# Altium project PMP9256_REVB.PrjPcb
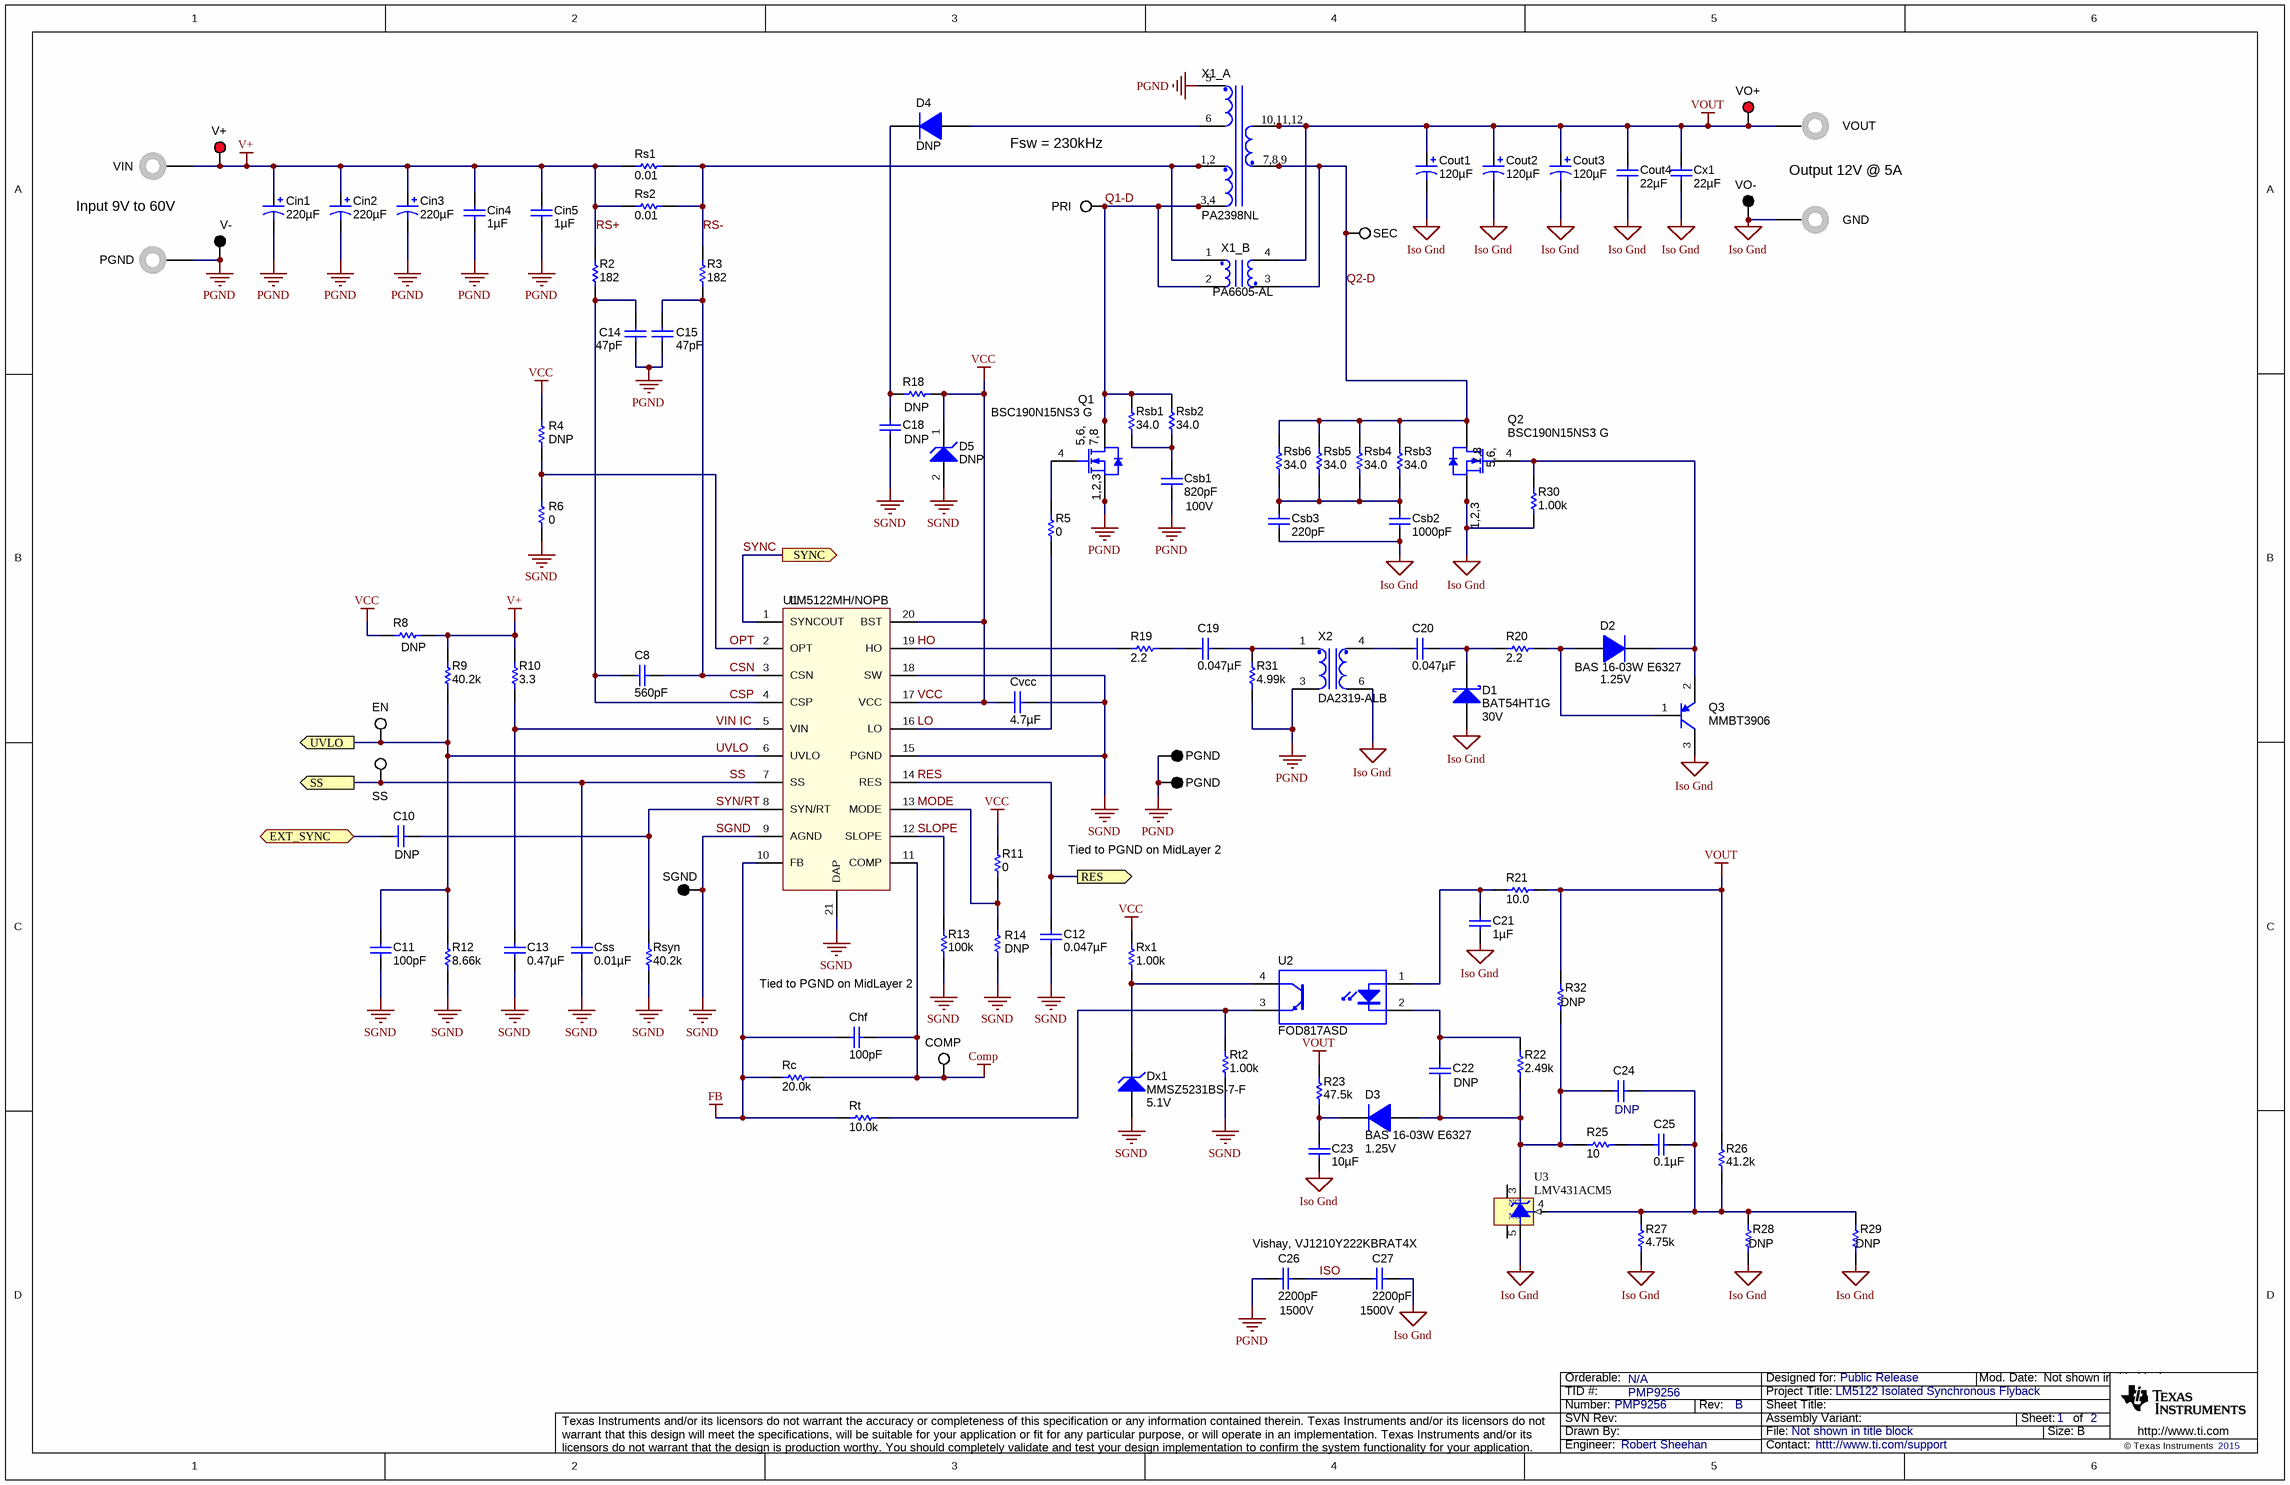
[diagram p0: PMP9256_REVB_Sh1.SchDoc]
CopyrightYear: 2015; EVM_Orderable: N/A; PCB_Layout: Robert Sheehan; PCB_Rev: B; PRJ_Customer: Public Release; PRJ_Engineer: Robert Sheehan; PRJ_Number: PMP9256; PRJ_Title: LM5122 Isolated Synchronous Flyback; SCH_Rev: B; TechSupport: httt://www.ti.com/support; TID: PMP9256
2 sheets, 119 parts. Net scope: flat (ports and power ports of the same name join across sheets).
Board file: PMP9256_REVB.PcbDoc
Sheets:
  PMP9256_REVB_Sh1.SchDoc
  PMP9256_REVB_Sh2.SchDoc

## Sheet PMP9256_REVB_Sh1.SchDoc
size 431 x 279 mm; Date: Not shown in title block; ApprovedBy: Not shown in title block; CheckedBy: Not shown in title block; Author: Not shown in title block; CompanyName: Not shown in title block; Engineer: Not shown in title block; Organization: Not shown in title block; Address1: Not shown in title block; Address2: Not shown in title block; Address3: Not shown in title block; Address4: Not shown in title block; DocumentNumber: 1; Revision: Use project parameter SCH_Rev; SheetNumber: 1; SheetTotal: 2; PageSetup: Record=PageOptions¦CenterHorizontal=True¦CenterVertical=True¦PrintScale=1.00¦XCorrection=1.00¦YCorrection=1.00¦PrintKind=0¦BorderSize=5000000¦LeftOffset=0¦BottomOffset=0¦Orientation=2¦PaperLength=1000¦PaperWidth=1000¦Scale=100¦PaperSource=15¦PrintQuality=600¦MediaType=1¦DitherType=10¦PaperKind=Letter¦PrintScaleMode=1

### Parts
C8  ValueDisplayed: 560pF  [0603L]  (hidden comment: GRM1885C1H561JA01D)
C10  DNP  [0603L]
C11  ValueDisplayed: 100pF  [0603L]  (hidden comment: GRM1885C1H101JA01D)
C12  ValueDisplayed: 0.047µF  [0603L]  (hidden comment: GRM188R71E473KA01D)
C13  ValueDisplayed: 0.47µF  [0603L]  (hidden comment: GRM188R71E474KA12D)
C14  ValueDisplayed: 47pF  [0603L]  (hidden comment: GRM1885C1H470JA01D)
C15  ValueDisplayed: 47pF  [0603L]  (hidden comment: GRM1885C1H470JA01D)
C18  DNP  [0805L]
C19  ValueDisplayed: 0.047µF  [0603L]  (hidden comment: GRM188R71E473KA01D)
C20  ValueDisplayed: 0.047µF  [0603L]  (hidden comment: GRM188R71E473KA01D)
C21  ValueDisplayed: 1µF  [0603L]  (hidden comment: C1608X7R1C105K)
C22  DNP  [0805L]
C23  ValueDisplayed: 10µF  [0805L]  (hidden comment: GRM21BR61C106KE15L)
C24  DNP  [0805L]
C25  ValueDisplayed: 0.1µF  [0603L]  (hidden comment: GRM188R71H104KA93D)
C26  Vishay, VJ1210Y222KBRAT4X  ValueDisplayed: 2200pF  Value2: 1500V  [1210L]
C27  ValueDisplayed: 2200pF  Value2: 1500V  [1210L]  (hidden comment: VJ1210Y222KXGAT5Z)
Chf  ValueDisplayed: 100pF  [0603L]  (hidden comment: GRM1885C1H101JA01D)
Cin1  ValueDisplayed: 220µF  [SM_RADIAL_H13]  (hidden comment: EEV-FK1J221Q)
Cin2  ValueDisplayed: 220µF  [SM_RADIAL_H13]  (hidden comment: EEV-FK1J221Q)
Cin3  ValueDisplayed: 220µF  [SM_RADIAL_H13]  (hidden comment: EEV-FK1J221Q)
Cin4  ValueDisplayed: 1µF  [1206L]  (hidden comment: C3216X7R2A105M)
Cin5  ValueDisplayed: 1µF  [1206L]  (hidden comment: C3216X7R2A105M)
COMP  5002  [Keystone5002]  (value not drawn)
Cout1  ValueDisplayed: 120µF  [CAPSMT_62_F61]  (hidden comment: 20SVPF120M)
Cout2  ValueDisplayed: 120µF  [CAPSMT_62_F61]  (hidden comment: 20SVPF120M)
Cout3  ValueDisplayed: 120µF  [CAPSMT_62_F61]  (hidden comment: 20SVPF120M)
Cout4  ValueDisplayed: 22µF  [1206L]  (hidden comment: GRM31CR61C226KE15L)
Csb1  ValueDisplayed: 820pF  Value2: 100V  [0603L]  (hidden comment: GRM188R72A821KA01D)
Csb2  value 1000pF  [0805]  (hidden comment: CGA4F3C0G2E102J085AA)
Csb3  value 220pF  [0603]  (hidden comment: CGA3E3C0G2E221J080AA)
Css  ValueDisplayed: 0.01µF  [0603L]  (hidden comment: GRM188R71H103KA01D)
Cvcc  ValueDisplayed: 4.7µF  [0603L]  (hidden comment: C0603C475K8PACTU)
Cx1  ValueDisplayed: 22µF  [1206L]  (hidden comment: GRM31CR61C226KE15L)
D1  BAT54HT1G  value 30V  [sod-323]
D2  BAS 16-03W E6327  value 1.25V  [sod-323]
D3  BAS 16-03W E6327  value 1.25V  [sod-323]
D4  DNP  [SOD-123]
D5  DNP  [SMA]
Dx1  MMSZ5231BS-7-F  value 5.1V  [sod-323]
EN  5002  [Keystone5002]  (value not drawn)
PGND  GND  [Keystone_575-4]
PGND2  PGND  [Keystone_575-4]
PGND3  PGND  [Keystone5011]
PGND4  PGND  [Keystone5011]
PRI  5002  [Keystone5002]  (value not drawn)
Q1  BSC190N15NS3 G  [PG-TDSON-8]
Q2  BSC190N15NS3 G  [PG-TDSON-8]
Q3  MMBT3906  [SOT-23]
R2  value 182  [0603L]  (hidden comment: CRCW0603182RFKEA)
R3  value 182  [0603L]  (hidden comment: CRCW0603182RFKEA)
R4  DNP  [0603L]
R5  value 0  [0603L]  (hidden comment: ERJ-3GEY0R00V)
R6  value 0  [0603L]  (hidden comment: ERJ-3GEY0R00V)
R8  DNP  [0603L]
R9  value 40.2k  [0603L]  (hidden comment: CRCW060340K2FKEA)
R10  value 3.3  [0603L]  (hidden comment: CRCW06033R30JNEA)
R11  value 0  [0603L]  (hidden comment: ERJ-3GEY0R00V)
R12  value 8.66k  [0603L]  (hidden comment: CRCW06038K66FKEA)
R13  value 100k  [0603L]  (hidden comment: CRCW0603100KFKEA)
R14  DNP  [0603L]
R18  DNP  [0603L]
R19  value 2.2  [0603L]  (hidden comment: CRCW06032R20JNEA)
R20  value 2.2  [0603L]  (hidden comment: CRCW06032R20JNEA)
R21  value 10.0  [0805L]  (hidden comment: CRCW080510R0FKEA)
R22  ValueDisplayed: 2.49k  [0603L]  (hidden comment: CRCW06032K49FKEA)
R23  value 47.5k  [0603L]  (hidden comment: CRCW060347K5FKEA)
R25  ValueDisplayed: 10  [0603L]  (hidden comment: CRCW060310R0JNEA)
R26  value 41.2k  [0603L]  (hidden comment: CRCW060341K2FKEA)
R27  ValueDisplayed: 4.75k  [0603L]  (hidden comment: CRCW06034K75FKEA)
R28  DNP  [0603L]
R29  DNP  [0603L]
R30  value 1.00k  [0603L]  (hidden comment: CRCW06031K00FKEA)
R31  value 4.99k  [0603L]  (hidden comment: CRCW06034K99FKEA)
R32  DNP  [0603L]
Rc  value 20.0k  [0603L]  (hidden comment: CRCW060320K0FKEA)
Rs1  value 0.01  [2010L]  (hidden comment: WSL2010R0100FEA18)
Rs2  value 0.01  [2010L]  (hidden comment: WSL2010R0100FEA18)
Rsb1  value 34.0  [1210L]  (hidden comment: ERJ-14NF34R0U)
Rsb2  value 34.0  [1210L]  (hidden comment: ERJ-14NF34R0U)
Rsb3  value 34.0  [1210L]  (hidden comment: ERJ-14NF34R0U)
Rsb4  value 34.0  [1210L]  (hidden comment: ERJ-14NF34R0U)
Rsb5  value 34.0  [1210L]  (hidden comment: ERJ-14NF34R0U)
Rsb6  value 34.0  [1210L]  (hidden comment: ERJ-14NF34R0U)
Rsyn  value 40.2k  [0603L]  (hidden comment: CRCW060340K2FKEA)
Rt  ValueDisplayed: 10.0k  [0603L]  (hidden comment: CRCW060310K0FKEA)
Rt2  ValueDisplayed: 1.00k  [0603L]  (hidden comment: CRCW06031K00FKEA)
Rx1  ValueDisplayed: 1.00k  [0603L]  (hidden comment: CRCW06031K00FKEA)
SEC  5002  [Keystone5002]  (value not drawn)
SGND  SGND  [Keystone5001]  (value not drawn)
SS  5002  [Keystone5002]  (value not drawn)
U1  LM5122MH/NOPB  [MXA20A_L]
U2  FOD817ASD  [N04C]
U3  LMV431ACM5  [MF05A_N]
V+  5010  [Keystone5010]  (value not drawn)
V-  5011  [Keystone5011]  (value not drawn)
VIN  575-4  [Keystone_575-4]  (value not drawn)
VO+  5010  [Keystone5010]  (value not drawn)
VO-  5011  [Keystone5011]  (value not drawn)
VOUT  Comment_1: Output 12V @ 5A  [Keystone_575-4]  (hidden comment: 575-4)
X1_A  PA2398NL
X1_B  PA6605-AL  [PA6605-AL]
X2  DA2319-ALB

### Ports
EXT_SYNC, RES, SS, SYNC (out), UVLO

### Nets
Comp: Chf.1 COMP.1 Rc.2 U1.11(COMP)
FB: Chf.2 Rc.1 Rt.2 U1.10(FB)
Iso Gnd: C21.2 C23.2 C27.1 Cout1.2(-) Cout2.2(-) Cout3.2(-) Cout4.2 Csb2.2 Csb3.2 Cx1.2 D1.2(A) PGND.1 Q2.1(S) Q2.2(S) Q2.3(S) Q3.3(C) R27.1 R28.1 R29.1 R30.1 U3.5(A) VO-.1 X2.6
PGND: C14.1 C15.2 C26.2 Cin1.2(-) Cin2.2(-) Cin3.2(-) Cin4.2 Cin5.2 Csb1.2 PGND2.1 PGND3.1 PGND4.1 Q1.1(S) Q1.2(S) Q1.3(S) R31.1 V-.1 X1_A.5 X2.3
SGND: C11.2 C12.2 C13.2 C18.2 Css.2 Cvcc.1 D5.2(A) Dx1.2(A) R6.1 R12.1 R13.1 R14.1 Rsyn.1 Rt2.1 SGND.1 U1.9(AGND) U1.15(PGND) U1.18(SW) U1.21(DAP)
V+: Cin1.1(+) Cin2.1(+) Cin3.1(+) Cin4.1 Cin5.1 R2.2 R8.1 R9.2 R10.2 Rs1.1 Rs2.1 V+.1 VIN.1
VCC: Cvcc.2 D5.1(K) R4.2 R8.2 R11.2 R18.1 Rx1.2 U1.17(VCC) U1.20(BST)
VOUT: Cout1.1(+) Cout2.1(+) Cout3.1(+) Cout4.1 Cx1.1 R21.2 R23.2 R26.2 R32.1 VO+.1 VOUT.1 X1_A.10 X1_A.11 X1_A.12 X1_B.4
CSN: C8.1 C15.1 R3.1 U1.3(CSN)
CSP: C8.2 C14.2 R2.1 U1.4(CSP)
EXT_SYNC: C10.2 ; port EXT_SYNC
HO: R19.1 U1.19(HO)
ISO: C26.1 C27.2
LO: R5.2 U1.16(LO)
MODE: R11.1 R14.2 U1.13(MODE)
OPT: R4.1 R6.2 U1.2(OPT)
Q1-D: PRI.1 Q1.5(D) Q1.6(D) Q1.7(D) Q1.8(D) Q1.9(D) Rsb1.2 Rsb2.2 X1_A.3 X1_A.4 X1_B.2
Q2-D: Q2.5(D) Q2.6(D) Q2.7(D) Q2.8(D) Q2.9(D) Rsb3.2 Rsb4.2 Rsb5.2 Rsb6.2 SEC.1 X1_A.7 X1_A.8 X1_A.9 X1_B.3
RES: C12.1 U1.14(RES) ; port RES
RS-: R3.2 Rs1.2 Rs2.2 X1_A.1 X1_A.2 X1_B.1
SLOPE: R13.2 U1.12(SLOPE)
SS: Css.1 SS.1 U1.7(SS) ; port SS
SYN/RT: C10.1 Rsyn.2 U1.8(SYN/RT)
SYNC: U1.1(SYNCOUT) ; port SYNC
UVLO: C11.1 EN.1 R9.1 R12.2 U1.6(UVLO) ; port UVLO
VIN IC: C13.1 R10.1 U1.5(VIN)
NetC18_1: C18.1 D4.1(K) R18.2
NetC19_1: C19.1 R31.2 X2.1
NetC19_2: C19.2 R19.2
NetC20_1: C20.1 D1.1(K) R20.1
NetC20_2: C20.2 X2.4
NetC21_1: C21.1 R21.1 U2.1(A)
NetC22_1: C22.1 C24.1 D3.2(A) R22.1 R25.1 R32.2 U3.3(K)
NetC22_2: C22.2 R22.2 U2.2(K)
NetC23_1: C23.1 D3.1(K) R23.1
NetC24_2: C24.2 C25.1 R26.1 R27.2 R28.2 R29.2 U3.4(REF)
NetC25_2: C25.2 R25.2
NetCsb1_1: Csb1.1 Rsb1.1 Rsb2.1
NetCsb2_1: Csb2.1 Csb3.1 Rsb3.1 Rsb4.1 Rsb5.1 Rsb6.1
NetD2_1: D2.1(K) Q2.4(G) Q3.2(E) R30.2
NetD2_2: D2.2(A) Q3.1(B) R20.2
NetD4_2: D4.2(A) X1_A.6
NetDx1_1: Dx1.1(K) Rx1.1 U2.4(C)
NetQ1_4: Q1.4(G) R5.1
NetRt_1: Rt.1 Rt2.2 U2.3(E)

Not connected (* = marked no-connect by the designer): U3 1(NC) 2(NC)

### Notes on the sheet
- (near X1_A) Fsw = 230kHz
- Input 9V to 60V
- RS+
- Tied to PGND on MidLayer 2

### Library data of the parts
C8 = GRM1885C1H561JA01D: CAP, CERM, 560pF, 50V, +/-5%, C0G/NP0, 0603; Manufacturer: MuRata; Polarized: N; CompType: Capacitor; U/M: EA; Cap_F: 0.00000000056; Tolerance_%: 5; Value1: Unknown; VDC_V: 50; TaMin_C: -55; TaMax_C: 125; Cap_Case: 0603
C10 = GRM1885C1H101JA01D: CAP, CERM, 100 pF, 50 V, +/- 5%, C0G/NP0, 0603; Manufacturer: MuRata; Polarized: N; CompType: Capacitor; Value: 100pF; U/M: EA; Cap_F: 0.0000000001; Tolerance_%: 5; Value1: Unknown; VDC_V: 50; Value2: 50V; TaMin_C: -55; TaMax_C: 125; Cap_Case: 0603
C11 Chf = GRM1885C1H101JA01D: CAP, CERM, 100pF, 50V, +/-5%, C0G/NP0, 0603; Manufacturer: MuRata; Polarized: N; CompType: Capacitor; U/M: EA; Cap_F: 0.0000000001; Tolerance_%: 5; VDC_V: 50; TaMin_C: -55; TaMax_C: 125; Cap_Case: 0603
C12 = GRM188R71E473KA01D: CAP, CERM, 0.047uF, 25V, +/-10%, X7R, 0603; Manufacturer: MuRata; Polarized: N; CompType: Capacitor; U/M: EA; Cap_F: 0.000000047; Tolerance_%: 10; VDC_V: 25; TaMin_C: -55; TaMax_C: 125; Cap_Case: 0603
C13 = GRM188R71E474KA12D: CAP, CERM, 0.47uF, 25V, +/-10%, X7R, 0603; Manufacturer: MuRata; Polarized: N; CompType: Capacitor; U/M: EA; Cap_F: 0.00000047; Tolerance_%: 10; Value1: Unknown; VDC_V: 25; TaMin_C: -55; TaMax_C: 125; Cap_Case: 0603
C14 C15 = GRM1885C1H470JA01D: CAP, CERM, 47pF, 50V, +/-5%, C0G/NP0, 0603; Manufacturer: MuRata; Polarized: N; CompType: Capacitor; U/M: EA; Cap_F: 0.000000000047; Tolerance_%: 5; Value1: Unknown; VDC_V: 50; TaMin_C: -55; TaMax_C: 125; Cap_Case: 0603
C18 = GRM21BR61C106KE15L: CAP, CERM, 10uF, 16V, +/-10%, X5R, 0805; Manufacturer: MuRata; Polarized: N; CompType: Capacitor; ValueDisplayed: 10µF; U/M: EA; Cap_F: 0.00001; Tolerance_%: 10; ESR_Ohm: 0.008; Value1: 0.008 ohm; VDC_V: 16; TaMin_C: -55; TaMax_C: 85; Cap_Case: 0805
C19 C20 = GRM188R71E473KA01D: CAP, CERM, 0.047 µF, 25 V, +/- 10%, X7R, 0603; Manufacturer: MuRata; Polarized: N; CompType: Capacitor; Value: 0.047uF; U/M: EA; Cap_F: 0.000000047; Tolerance_%: 10; Value1: Unknown; VDC_V: 25; Value2: 25V; TaMin_C: -55; TaMax_C: 125; Cap_Case: 0603
C21 = C1608X7R1C105K: CAP, CERM, 1uF, 16V, +/-10%, X7R, 0603; Manufacturer: TDK; Polarized: N; CompType: Capacitor; U/M: EA; Cap_F: 0.000001; Tolerance_%: 10; ESR_Ohm: 0.0057; Value1: 0.0057 ohm; VDC_V: 16; TaMin_C: -55; TaMax_C: 125; Cap_Case: 0603
C22 C24 = C2012Y5V1H105Z: Capacitor; Manufacturer: TDK; Cap_Case: 0805; Polarized: N; Tolerance_%: 80; VDC_V: 50; Cap_F: 1.0E-6; Value: 100pF; Value1: Ohm; Value2: 50V; Dielectric: Y5V
C23 = GRM21BR61C106KE15L: CAP, CERM, 10uF, 16V, +/-10%, X5R, 0805; Manufacturer: MuRata; Polarized: N; CompType: Capacitor; U/M: EA; Cap_F: 0.00001; Tolerance_%: 10; ESR_Ohm: 0.008; Value1: 0.008 ohm; VDC_V: 16; TaMin_C: -55; TaMax_C: 85; Cap_Case: 0805
C25 = GRM188R71H104KA93D: CAP, CERM, 0.1uF, 50V, +/-10%, X7R, 0603; Manufacturer: MuRata; Polarized: N; CompType: Capacitor; U/M: EA; Cap_F: 0.0000001; Tolerance_%: 10; Value1: Unknown; VDC_V: 50; TaMin_C: -55; TaMax_C: 125; Cap_Case: 0603
C26 C27 = VJ1210Y222KXGAT5Z: CAP, CERM, 2200pF, 1000V, +/-10%, X7R, 1210; Manufacturer: Vishay-Vitramon; Polarized: N; CompType: Capacitor; U/M: EA; Cap_F: 0.0000000022; Tolerance_%: 10; VDC_V: 1000; TaMin_C: -55; TaMax_C: 125; Cap_Case: 1210
Cin1-Cin3 = EEV-FK1J221Q: CAP, AL, 220uF, 63V, +/-20%, 0.16 ohm, SMD; Manufacturer: Panasonic; Polarized: Y; CompType: Capacitor; U/M: EA; Cap_F: 0.00022; Tolerance_%: 20; VDC_V: 63; ESR_Ohm: 0.16; IRMS_A: 0.8; TaMin_C: -55; TaMax_C: 105; Cap_Case: H13
Cin4 Cin5 = C3216X7R2A105M: CAP, CERM, 1uF, 100V, +/-20%, C Series, 1206; Manufacturer: TDK; Polarized: N; CompType: Capacitor; U/M: EA; Cap_F: 0.000001; Tolerance_%: 20; ESR_Ohm: 0.006; Value1: 0.006 ohm; VDC_V: 100; IRMS_A: 4.5; TaMin_C: -55; TaMax_C: 125; Cap_Case: 1206
COMP EN SS = 5002: Test Point, TH, Miniature, White; Manufacturer: Keystone; CompType: Test Point Loop; U/M: EA
Cout1-Cout3 = 20SVPF120M: CAP, AL, 120uF, 20V, +/-20%, 0.025 ohm, SMD; Manufacturer: Sanyo; Polarized: Y; CompType: Capacitor; U/M: EA; Cap_F: 0.00012; Tolerance_%: 20; ESR_Ohm: 0.025; IRMS_A: 3.2; TaMin_C: -55; TaMax_C: 105
Cout4 Cx1 = GRM31CR61C226KE15L: CAP, CERM, 22uF, 16V, +/-10%, X5R, 1206; Manufacturer: MuRata; Polarized: N; CompType: Capacitor; U/M: EA; Cap_F: 0.000022; Tolerance_%: 10; Value1: Unknown; VDC_V: 16; TaMin_C: -55; TaMax_C: 85; Cap_Case: 1206
Csb1 = GRM188R72A821KA01D: CAP, CERM, 820 pF, 100 V, +/- 10%, X7R, 0603; Manufacturer: MuRata; Polarized: N; CompType: Capacitor; Value: 820pF; U/M: EA; Cap_F: 0.00000000082; Tolerance_%: 10; Value1: Unknown; VDC_V: 100; TaMin_C: -55; TaMax_C: 125; Cap_Case: 0603
Csb2 = CGA4F3C0G2E102J: CAP, CERM, 4.7uF, 100V, +/-20%, X7S, 1210; Manufacturer: TDK Corporation; Tolerance_%: ±5%; VDC_V: 250V; TempCo: C0G, NP0
Csb3 = CGA3E3C0G2E221J: CAP, CERM, 4.7uF, 100V, +/-20%, X7S, 1210; Manufacturer: TDK Corporation; Tolerance_%: ±5%; VDC_V: 250V; TempCo: C0G, NP0
Css = GRM188R71H103KA01D: CAP, CERM, 0.01uF, 50V, +/-10%, X7R, 0603; Manufacturer: MuRata; Polarized: N; CompType: Capacitor; U/M: EA; Cap_F: 0.00000001; Tolerance_%: 10; Value1: Unknown; VDC_V: 50; TaMin_C: -55; TaMax_C: 125; Cap_Case: 0603
Cvcc = C0603C475K8PACTU: CAP, CERM, 4.7uF, 10V, +/-10%, X5R, 0603; Manufacturer: Kemet; Polarized: N; CompType: Capacitor; U/M: EA; Cap_F: 0.0000047; Tolerance_%: 10; ESR_Ohm: 0.006; Value1: 0.006 ohm; IRMS_A: 7.24; TaMin_C: -55; TaMax_C: 85; Cap_Case: 0603
D1 = BAT54HT1G: Diode, Schottky, 30V, 0.2A, SOD-323; Manufacturer: ON Semiconductor; U/M: EA; Vf_V: 0.35; Value2: 0.35V; Io_A: 0.2; Vr_V: 30
D2 D3 = Diode: DIODE SWITCH 80V 0.25A SOD323-2; Manufacturer: Infineon Technologies; U/M: EA; Io_A: 0.25; Vf_V: 1.25; Vr_V: 80
D4 = BAV21W-7-F: Diode, Switching, 200V, 0.2A, SOD-123; Manufacturer: Diodes Inc.; U/M: EA; Vf_V: 1.25; Value2: 1.25V; Io_A: 0.2; Vr_V: 200; TJmax_C: 150
D5 = BZG03C15G: Diode, Zener, 15V, 1.5W, SMA; Manufacturer: ON Semiconductor; U/M: EA; Power_W: 1.5; Vz_V: 15
Dx1 = MMSZ5231BS-7-F: Diode, Zener, 5.1 V, 200 mW, SOD-323; Manufacturer: Diodes Inc.; U/M: EA; Power_W: 0.2; Vz_V: 5.1; Value1: 0.2W; RJA_CperW: 350; SymbolCreator: a0412235
PGND PGND2 VIN VOUT = 575-4: Standard Banana Jack, Uninsulated, 5.5mm; Manufacturer: Keystone; CompType: Connector; U/M: EA
PGND3 PGND4 V- VO- = 5011: Test Point, TH, Multipurpose, Black; Manufacturer: Keystone; CompType: Test Point Loop; U/M: EA
PRI SEC = 5002: Test Point, Miniature, White, TH; Manufacturer: Keystone; CompType: Test Point Loop; U/M: EA
Q1 Q2 = BSC190N15NS3 G: MOSFET, N-CH, 150 V, 50 A, PG-TDSON-8; Manufacturer: Infineon Technologies; Alternate Manufacturer: None; Value: 150V; U/M: EA; ChType: N; VdsMax_V: 150; Value1: 0.02 ohm; Rdson45_ohm: 0.02; Value2: 23 nC; QgTyp_nC: 23; Vgs_V: 20; IdsMax_A: 50
Q3 = MMBT3906, Fairchild Semiconductor: Transistor, PNP, 40V, 0.2A, SOT-23; Alternate Manufacturer: None; CompType: BJT; U/M: EA; PNP: 1; NPN: 0; Vceo_V: 40; Vcesat1_V: 0.25; Value: 0.25V; IcRated_A: 0.2; HfeMax: 300
R2 R3 = CRCW0603182RFKEA: RES, 182 ohm, 1%, 0.1W, 0603; Manufacturer: Vishay-Dale; CompType: Resistor; Value_Code: 182R; Tolerance_%: 1; Power_W: 0.1; VDC_V: 75; TempCo: 100 ppm/C; EIA_Code: E96; U/M: EA
R4 = CRCW0603158KFKEA: RES, 158 k, 1%, 0.1 W, 0603; Manufacturer: Vishay-Dale; CompType: Resistor; Value: 158k; Res_ohm: 158000; Tolerance_%: 1; Power_W: 0.1; Value2: 0.1W; VDC_V: 75; TempCo: 100 ppm/C; EIA_Code: E96; U/M: EA
R5 R6 R11 = ERJ-3GEY0R00V: RES, 0 ohm, 5%, 0.1W, 0603; Manufacturer: Panasonic; CompType: Resistor; Value_Code: 0000; Tolerance_%: 5; Power_W: 0.1; VDC_V: 50; TempCo: 600 ppm/C; EIA_Code: E24; U/M: EA
R8 R14 = ERJ-3GEY0R00V: RES, 0, 5%, 0.1 W, 0603; Manufacturer: Panasonic; CompType: Resistor; Value: 0; Value_Code: 0000; Tolerance_%: 5; Power_W: 0.1; Value2: 0.1W; VDC_V: 50; TempCo: 600 ppm/C; EIA_Code: E24; U/M: EA
R9 Rsyn = CRCW060340K2FKEA: RES, 40.2k ohm, 1%, 0.1W, 0603; Manufacturer: Vishay-Dale; CompType: Resistor; Res_ohm: 40200; Value_Code: 40k2; Tolerance_%: 1; Power_W: 0.1; VDC_V: 75; TempCo: 100 ppm/C; EIA_Code: E96; U/M: EA
R10 = CRCW06033R30JNEA: RES, 3.3 ohm, 5%, 0.1W, 0603; Manufacturer: Vishay-Dale; CompType: Resistor; Value_Code: 3R30; Tolerance_%: 5; Power_W: 0.1; VDC_V: 75; TempCo: 200 ppm/C; EIA_Code: E24; U/M: EA
R12 = CRCW06038K66FKEA: RES, 8.66k ohm, 1%, 0.1W, 0603; Manufacturer: Vishay-Dale; CompType: Resistor; Res_ohm: 8660; Value_Code: 8k66; Tolerance_%: 1; Power_W: 0.1; VDC_V: 75; TempCo: 100 ppm/C; EIA_Code: E96; U/M: EA
R13 = CRCW0603100KFKEA: RES, 100k ohm, 1%, 0.1W, 0603; Manufacturer: Vishay-Dale; CompType: Resistor; Res_ohm: 100000; Tolerance_%: 1; Power_W: 0.1; VDC_V: 75; TempCo: 100 ppm/C; EIA_Code: E96; U/M: EA
R18 = CRCW06030000Z0EA: RES, 0 ohm, 5%, 0.1W, 0603; Manufacturer: Vishay-Dale; Alternate Manufacturer: Any; Alternate PartNumber: Equivalent; CompType: Resistor; Value: 0; Value_Code: 0000; Tolerance_%: 5; Power_W: 0.1; VDC_V: 75; TempCo: 200 ppm/C; EIA_Code: E24; U/M: EA
R19 R20 = CRCW06032R20JNEA: RES, 2.2 ohm, 5%, 0.1W, 0603; Manufacturer: Vishay-Dale; CompType: Resistor; Value_Code: 2R20; Tolerance_%: 5; Power_W: 0.1; VDC_V: 75; TempCo: 200 ppm/C; EIA_Code: E24; U/M: EA
R21 = CRCW080510R0FKEA: RES, 10.0 ohm, 1%, 0.125W, 0805; Manufacturer: Vishay-Dale; CompType: Resistor; Res_ohm: 10; Value_Code: 10R0; Tolerance_%: 1; Power_W: 0.125; VDC_V: 150; TempCo: 100 ppm/C; EIA_Code: E96; U/M: EA
R22 = CRCW06032K49FKEA: RES, 2.49 k, 1%, 0.1 W, 0603; Manufacturer: Vishay-Dale; CompType: Resistor; Value: 2.49k; Res_ohm: 2490; Value_Code: 2k49; Tolerance_%: 1; Power_W: 0.1; Value2: 0.1W; VDC_V: 75; TempCo: 100 ppm/C; EIA_Code: E96; U/M: EA
R23 = CRCW060347K5FKEA: RES, 47.5k ohm, 1%, 0.1W, 0603; Manufacturer: Vishay-Dale; CompType: Resistor; Res_ohm: 47500; Value_Code: 47k5; Tolerance_%: 1; Power_W: 0.1; VDC_V: 75; TempCo: 100 ppm/C; EIA_Code: E96; U/M: EA
R25 = CRCW060310R0JNEA: RES, 10, 5%, 0.1 W, 0603; Manufacturer: Vishay-Dale; CompType: Resistor; Value: 10; Value_Code: 10R0; Tolerance_%: 5; Power_W: 0.1; Value2: 0.1W; VDC_V: 75; TempCo: 200 ppm/C; EIA_Code: E24; U/M: EA
R26 = CRCW060341K2FKEA: RES, 41.2k ohm, 1%, 0.1W, 0603; Manufacturer: Vishay-Dale; CompType: Resistor; Res_ohm: 41200; Value_Code: 41k2; Tolerance_%: 1; Power_W: 0.1; VDC_V: 75; TempCo: 100 ppm/C; EIA_Code: E96; U/M: EA
R27 = CRCW06034K75FKEA: RES, 4.75 k, 1%, 0.1 W, 0603; Manufacturer: Vishay-Dale; CompType: Resistor; Value: 4.75k; Res_ohm: 4750; Value_Code: 4k75; Tolerance_%: 1; Power_W: 0.1; Value2: 0.1W; VDC_V: 75; TempCo: 100 ppm/C; EIA_Code: E96; U/M: EA
R28 = CRCW06032K26FKEA: RES, 2.26k ohm, 1%, 0.1W, 0603; Manufacturer: Vishay-Dale; CompType: Resistor; Res_ohm: 2260; Value_Code: 2k26; Tolerance_%: 1; Power_W: 0.1; VDC_V: 75; TempCo: 100 ppm/C; EIA_Code: E96; U/M: EA
R29 = CRCW0603442RFKEA: RES, 442 ohm, 1%, 0.1W, 0603; Manufacturer: Vishay-Dale; CompType: Resistor; Value: 442; Value_Code: 442R; Tolerance_%: 1; Power_W: 0.1; VDC_V: 75; TempCo: 100 ppm/C; EIA_Code: E96; U/M: EA
R30 = CRCW06031K00FKEA: RES, 1.00k ohm, 1%, 0.1W, 0603; Manufacturer: Vishay-Dale; CompType: Resistor; Res_ohm: 1000; Value_Code: 1k00; Tolerance_%: 1; Power_W: 0.1; VDC_V: 75; TempCo: 100 ppm/C; EIA_Code: E96; U/M: EA
R31 = CRCW06034K99FKEA: RES, 4.99k ohm, 1%, 0.1W, 0603; Manufacturer: Vishay-Dale; CompType: Resistor; Res_ohm: 4990; Value_Code: 4k99; Tolerance_%: 1; Power_W: 0.1; VDC_V: 75; TempCo: 100 ppm/C; EIA_Code: E96; U/M: EA
R32 = CRCW060310K0FKEA: RES, 10.0k ohm, 1%, 0.1W, 0603; Manufacturer: Vishay-Dale; CompType: Resistor; Res_ohm: 10000; Value_Code: 10k0; Tolerance_%: 1; Power_W: 0.1; VDC_V: 75; TempCo: 100 ppm/C; EIA_Code: E96; U/M: EA
Rc = CRCW060320K0FKEA: RES, 20.0k ohm, 1%, 0.1W, 0603; Manufacturer: Vishay-Dale; CompType: Resistor; Res_ohm: 20000; Value_Code: 20k0; Tolerance_%: 1; Power_W: 0.1; VDC_V: 75; TempCo: 100 ppm/C; EIA_Code: E96; U/M: EA
Rs1 Rs2 = WSL2010R0100FEA18: RES, 0.01 ohm, 1%, 1W, 2010; Manufacturer: Vishay-Dale; CompType: Resistor; Value_Code: R010; Tolerance_%: 1; TempCo: 75 ppm/C; EIA_Code: E96; U/M: EA
Rsb1-Rsb6 = MCR25JZHJ000: RES 34 OHM 1/2W 1% 1210 SMD; Manufacturer: Panasonic Electronic Components; CompType: Resistor; Res_ohm: 34; Value_Code: 0034; Tolerance_%: 1; Power_W: .5; Value2: 0.5W; VDC_V: 200; TempCo: 20 ppm/C; EIA_Code: E24; U/M: EA
Rt = CRCW060310K0FKEA: RES, 10.0 k, 1%, 0.1 W, 0603; Manufacturer: Vishay-Dale; CompType: Resistor; Res_ohm: 10000; Value_Code: 10k0; Tolerance_%: 1; Power_W: 0.1; Value2: 0.1W; VDC_V: 75; TempCo: 100 ppm/C; EIA_Code: E96; U/M: EA; Value: 10.0k
Rt2 Rx1 = CRCW06031K00FKEA: RES, 1.00 k, 1%, 0.1 W, 0603; Manufacturer: Vishay-Dale; CompType: Resistor; Value: 1.00k; Res_ohm: 1000; Value_Code: 1k00; Tolerance_%: 1; Power_W: 0.1; Value2: 0.1W; VDC_V: 75; TempCo: 100 ppm/C; EIA_Code: E96; U/M: EA
SGND = 5001: Test Point, TH, Miniature, Black; Manufacturer: Keystone; CompType: Test Point Loop; U/M: EA
U1 = LM5122MH/NOPB: Wide Input Synchronous Boost Controller with Multiple Phase Capability, PWP0020A; Manufacturer: Texas Instruments; SymbolCreator: a0411947; CompType: IC; U/M: EA
U2 = FOD817ASD: IC, Optocoupler, 5000V, 80-160% CTR; Manufacturer: Fairchild Semiconductor; U/M: EA
U3 = LMV431ACM5: Low-Voltage (1.24V) Adjustable Precision Shunt Regulator, 5-pin SOT-23; Manufacturer: Texas Instruments; PackageTopMarking: N09A*XTT; PowerWise: N; CompType: MiscPower
V+ VO+ = 5010: Test Point, Multipurpose, Red, TH; Manufacturer: Keystone; CompType: Test Point Loop; U/M: EA
X1_A = PA2398: Transformer, 307 uH, SMT; Manufacturer: Pulse Electronics; SymbolVersion: use current date i.e. 2008-05-20; SymbolCreator: Use a-id; U/M: EA; Value: 307 uH
X1_B = PA6605-AL: Transformer, 10 uH, SMT; Manufacturer: Coilcraft; SymbolCreator: Altium; U/M: EA; DCR_Ohm: 0.0047; LeakageL: 0.13 uH; Value: 10 uH
X2 = DA2319-ALB: Transformer, 296 uH, SMT; Manufacturer: Coilcraft; SymbolVersion: use current date i.e. 2008-05-20; SymbolCreator: Use a-id; U/M: EA; Value: 296 uH

## Sheet PMP9256_REVB_Sh2.SchDoc
size 431 x 279 mm; Date: Not shown in title block; ApprovedBy: Not shown in title block; CheckedBy: Not shown in title block; Author: Not shown in title block; CompanyName: Not shown in title block; Engineer: Not shown in title block; Organization: Not shown in title block; Address1: Not shown in title block; Address2: Not shown in title block; Address3: Not shown in title block; Address4: Not shown in title block; DocumentNumber: 2; Revision: Use project parameter SCH_Rev; SheetNumber: 2; SheetTotal: 2; PageSetup: Record=PageOptions¦CenterHorizontal=True¦CenterVertical=True¦PrintScale=1.00¦XCorrection=1.00¦YCorrection=1.00¦PrintKind=0¦BorderSize=5000000¦LeftOffset=0¦BottomOffset=0¦Orientation=2¦PaperLength=1000¦PaperWidth=1000¦Scale=100¦PaperSource=15¦PrintQuality=600¦MediaType=1¦DitherType=10¦PaperKind=Letter¦PrintScaleMode=1
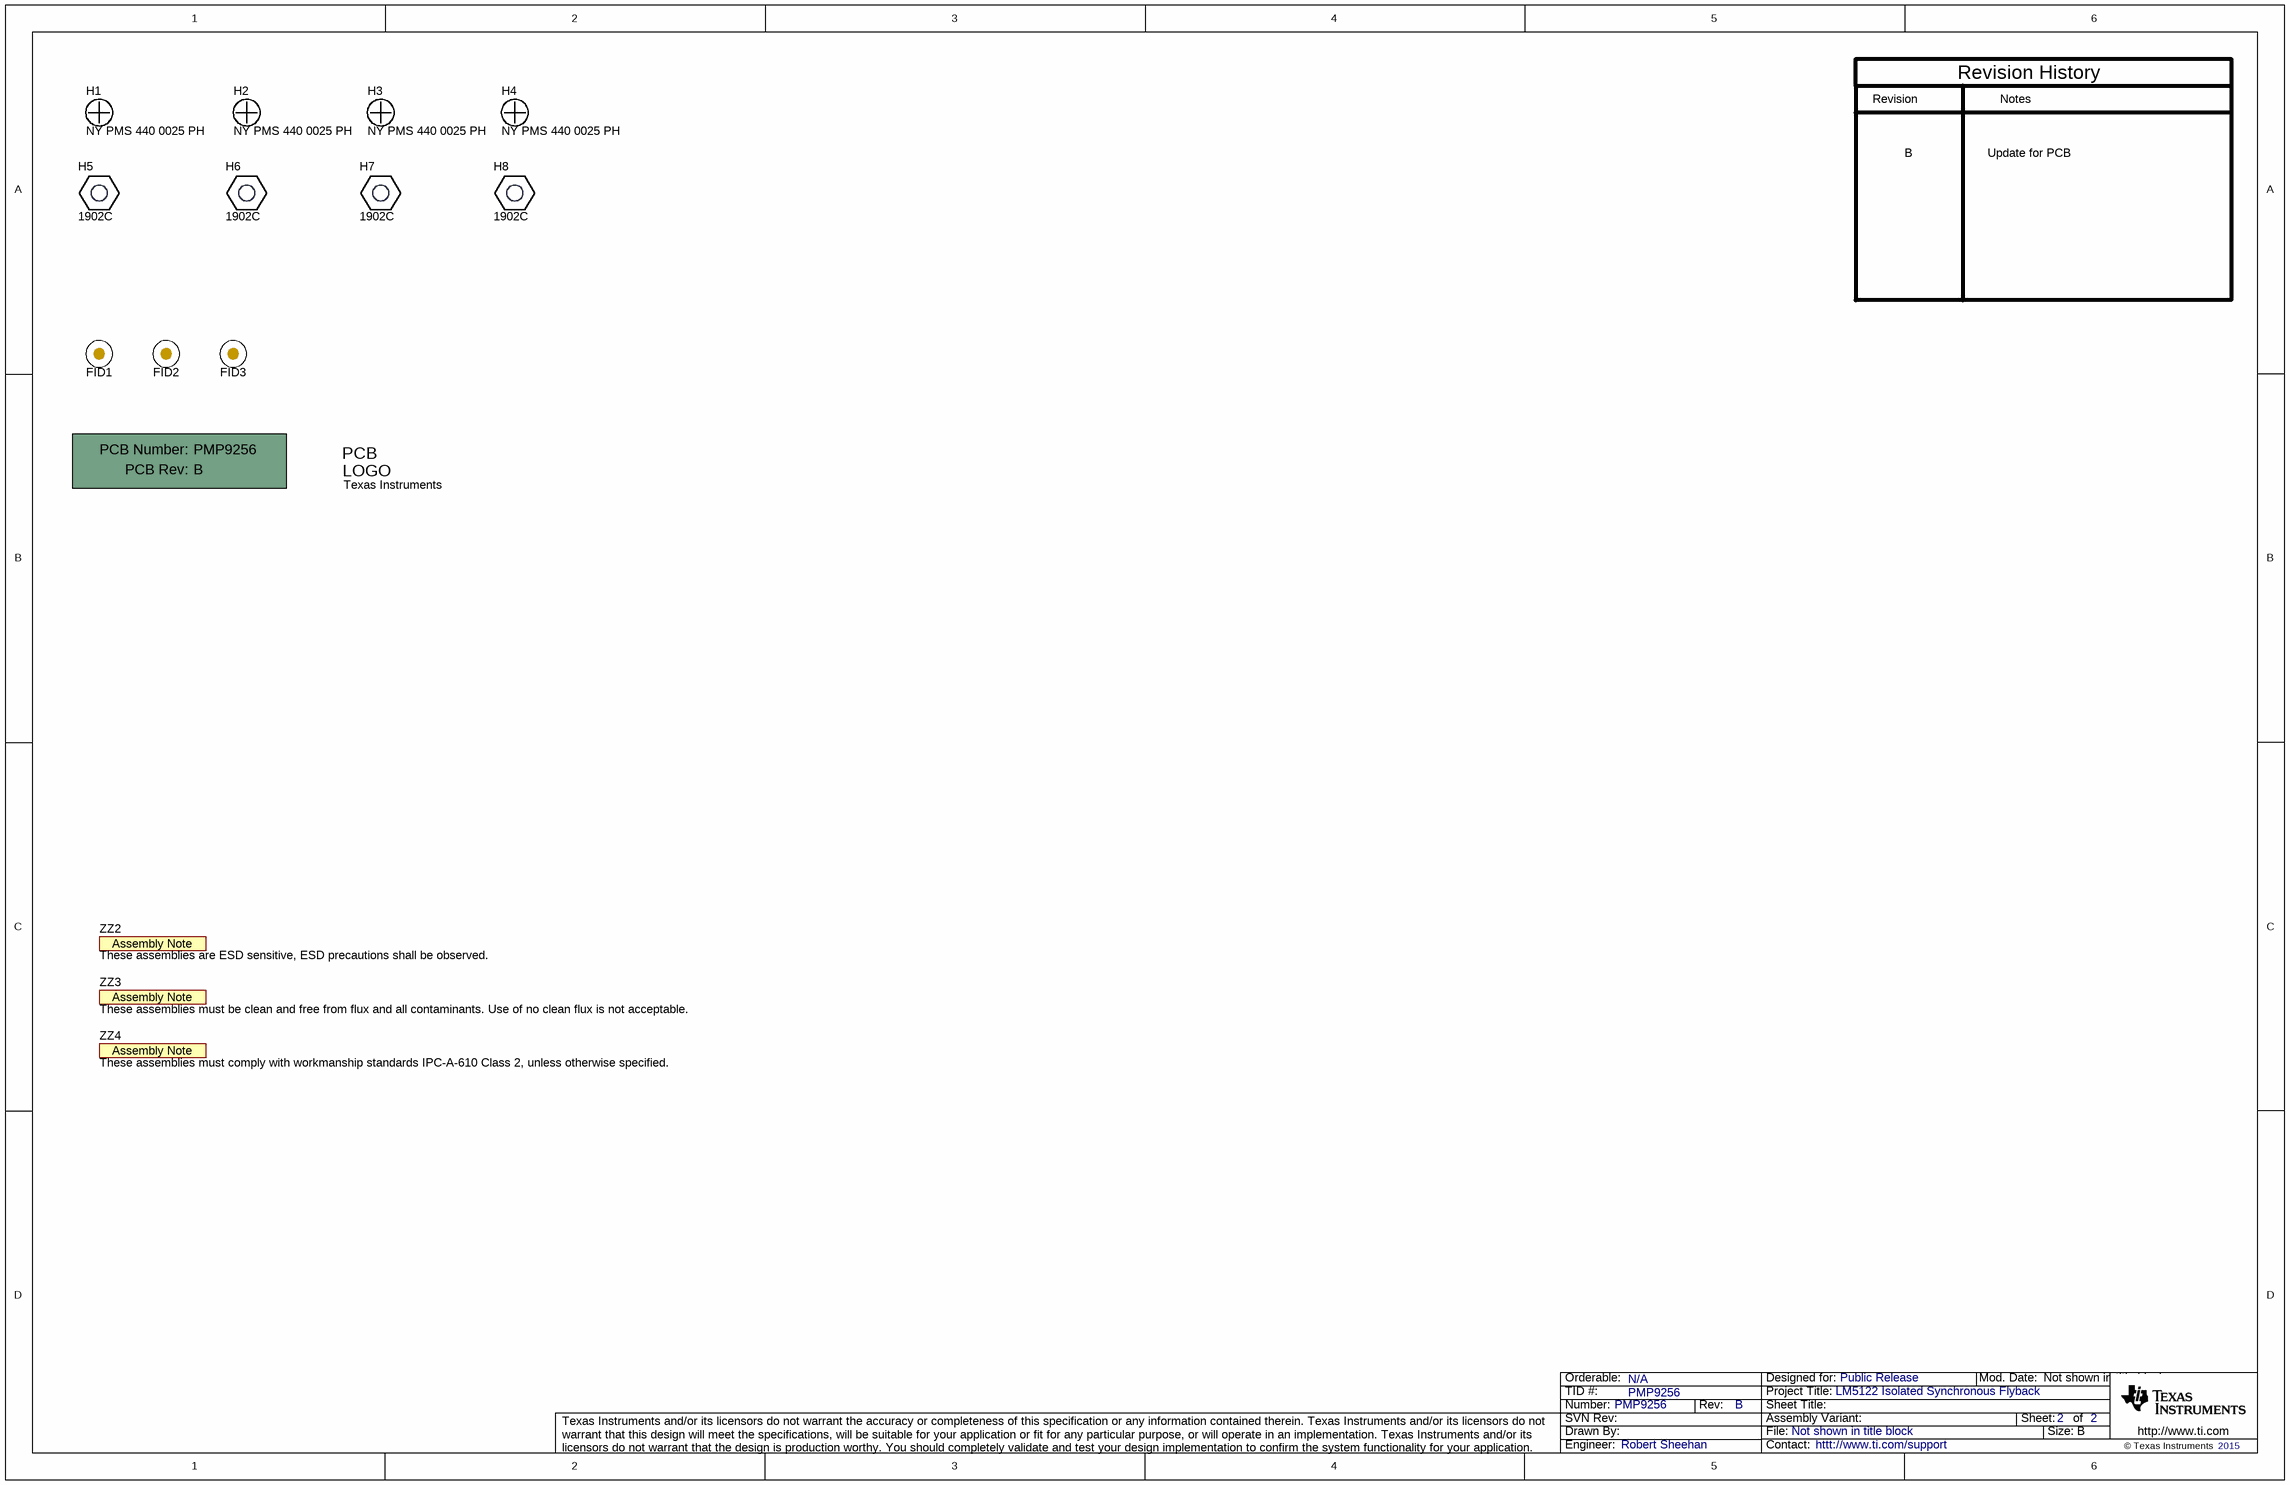
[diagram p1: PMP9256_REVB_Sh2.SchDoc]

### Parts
!PCB  Printed Circuit Board  (value not drawn)  (mechanical)
FID1  Fiducial  [Fiducial10-20]  (value not drawn)
FID2  Fiducial  [Fiducial10-20]  (value not drawn)
FID3  Fiducial  [Fiducial10-20]  (value not drawn)
H1  NY PMS 440 0025 PH  [NY PMS 440 0025 PH]
H2  NY PMS 440 0025 PH  [NY PMS 440 0025 PH]
H3  NY PMS 440 0025 PH  [NY PMS 440 0025 PH]
H4  NY PMS 440 0025 PH  [NY PMS 440 0025 PH]
H5  1902C  [Keystone_1902C]
H6  1902C  [Keystone_1902C]
H7  1902C  [Keystone_1902C]
H8  1902C  [Keystone_1902C]
Logo1  Texas Instruments  [TI_Stacked_SolderMask_Small]  (no BOM)
ZZ2  These assemblies are ESD sensitive, ESD precautions shall be observed.  [AssemblyNote]  (no BOM)
ZZ3  These assemblies must be clean and free from flux and all contaminants. Use of no clean flux is not acceptable.  [AssemblyNote]  (no BOM)
ZZ4  These assemblies must comply with workmanship standards IPC-A-610 Class 2, unless otherwise specified.  [AssemblyNote]  (no BOM)

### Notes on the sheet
- Revision
- Notes
- Revision History
- B
- Update for PCB

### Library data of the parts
!PCB = PCB: Manufacturer: Any; PartNumber: PMP9256; SymbolCreator: a0412235
FID1-FID3 = Fiducial: Fiducial mark.  There is nothing to buy or mount.; SymbolCreator: codlsc
H1-H4 = NY PMS 440 0025 PH: Machine Screw, Round, #4-40 x 1/4, Nylon, Philips panhead; Manufacturer: B&F Fastener Supply; CompType: Hardware; SymbolCreator: codlsc; U/M: EA
H5-H8 = 1902C: Standoff, Hex, 0.5"L #4-40 Nylon; Manufacturer: Keystone; CompType: Hardware
Logo1 = TI_Logo: Texas Instrument Corporate Signature; SymbolCreator: codlsc
ZZ2-ZZ4 = AssemblyNote: SymbolCreator: codlsc

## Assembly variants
001: not fitted C10 C18 C22 C24 D4 D5 FID1 FID2 FID3 R4 R8 R14 R18 R28 R29 R32 X1_A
